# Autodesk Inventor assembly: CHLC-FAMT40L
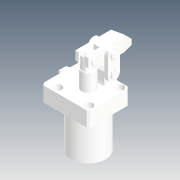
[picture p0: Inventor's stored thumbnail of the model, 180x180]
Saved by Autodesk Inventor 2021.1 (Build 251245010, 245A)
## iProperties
Created: 2019-04
Part Number: CHLC-FAMT40L
Description: STEP AP214
Document SubType Name: Assembly
Designer: user
Title: CHLC-FAMT40L.STEP
Revision Number: ÈÎºÎ
Sending System: SolidWorks 2016
Preprocessor: SwSTEP 2.0
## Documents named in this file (11)
- D:\Vault_2016\Projekty\Clamptek\Hydraulic\CHLC\CHLC-40\Inventor\CHLC-FAMT40L\CHLC-FAMT40L.iam
- D:\Vault_2016\Projekty\Clamptek\Hydraulic\CHLC\CHLC-40\Inventor\CHLC-FAMT40L\benti.ipt
- D:\Vault_2016\Projekty\Clamptek\Hydraulic\CHLC\CHLC-40\Inventor\CHLC-FAMT40L\CHLC-40-01.ipt
- D:\Vault_2016\Projekty\Clamptek\Hydraulic\CHLC\CHLC-40\Inventor\CHLC-FAMT40L\CHLC-40-02.ipt
- D:\Vault_2016\Projekty\Clamptek\Hydraulic\CHLC\CHLC-40\Inventor\CHLC-FAMT40L\CHLC-40-03.ipt
- D:\Vault_2016\Projekty\Clamptek\Hydraulic\CHLC\CHLC-40\Inventor\CHLC-FAMT40L\CHLC-40-04.ipt
- D:\Vault_2016\Projekty\Clamptek\Hydraulic\CHLC\CHLC-40\Inventor\CHLC-FAMT40L\CHLC-40-06.ipt
- D:\Vault_2016\Projekty\Clamptek\Hydraulic\CHLC\CHLC-40\Inventor\CHLC-FAMT40L\CZL20µ÷ËÙ·§.iam
- D:\Vault_2016\Projekty\Clamptek\Hydraulic\CHLC\CHLC-40\Inventor\CHLC-FAMT40L\M6LS.ipt
- D:\Vault_2016\Projekty\Clamptek\Hydraulic\CHLC\CHLC-40\Inventor\CHLC-FAMT40L\ZHIC.ipt
- D:\Vault_2016\Projekty\Clamptek\Hydraulic\CHLC\CHLC-40\Inventor\CHLC-FAMT40L\CHLC-40-08.ipt
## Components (19 placed, 19 different names)
1. benti_1
2. CHLC-40-01_2
3. CHLC-40-02_3
4. CHLC-40-03_4
5. CHLC-40-04_5
6. CHLC-40-06_6
7. CZL20µ÷ËÙ·§_7 [sub-assembly]
8. M6LS_8
9. ZHIC_9
10. CHLC-40-08_10
11. CHLC-40-03_11
12. CHLC-40-06_12
13. CHLC-40-06_13
14. CHLC-40-06_14
15. CHLC-40-06_15
16. CHLC-40-06_16
17. CHLC-40-02_17
18. M6LS_18
19. M6LS_19
